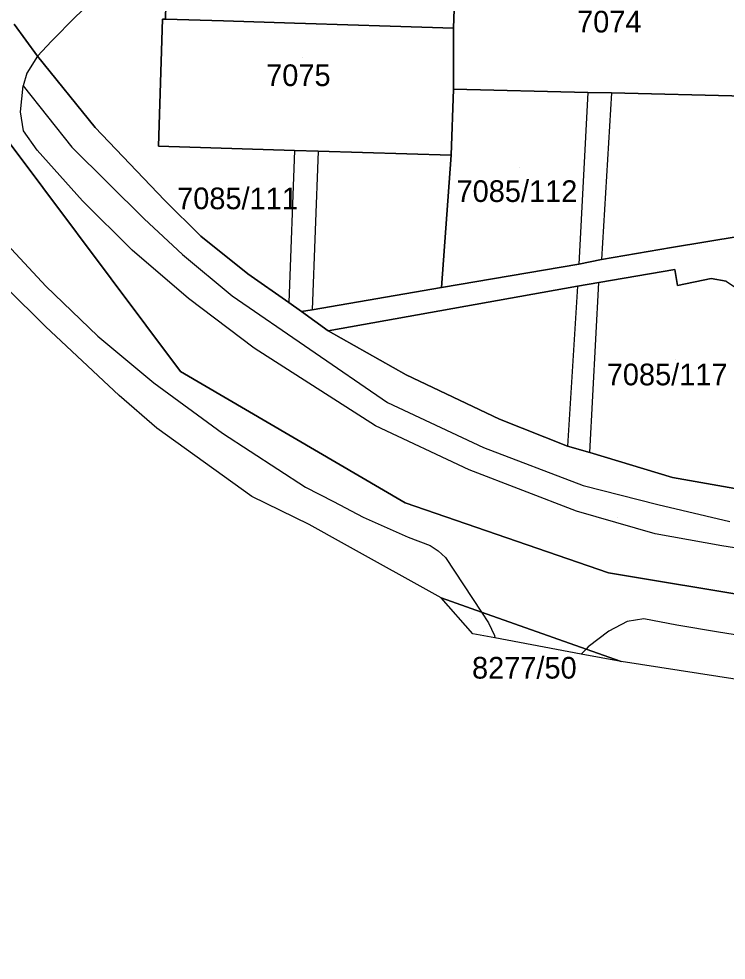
# Model space of a CAD drawing. Extents: x -266199 to -261993, y -1239047 to -1235108.
# Drawn here: x -263858.6 to -263793.2, y -1236874.8 to -1236787.9 of the extents above; entities that cross this region are included whole.
import ezdxf

# ---------------------------------------------------------------- set-up
doc = ezdxf.new("R2010")
doc.units = 0
for name, color, linetype in [('body_kn', 7, 'Continuous'), ('kladpar_druhypozemkov', 7, 'Continuous'), ('kladpar_hranice', 7, 'Continuous'), ('kladpar_parcelnecisla', 7, 'Continuous'), ('kladpar_plochy', 7, 'Continuous'), ('kladpar_sipky', 7, 'Continuous'), ('zappar_hrandruhpozemk', 7, 'Continuous'), ('zuob_linie', 7, 'Continuous'), ('zuob_plochy', 7, 'Continuous')]:
    doc.layers.add(name, color=color, linetype=linetype)

msp = doc.modelspace()

# ---------------------------------------------------------------- linework, layer by layer
at = {"layer": 'body_kn'}
for p, q in [((-263845.31, -1236787.91), (-263845.31, -1236787.91)), ((-263845.01, -1236787.92), (-263845.01, -1236787.92)), ((-263839.66, -1236788.08), (-263839.66, -1236788.08)), ((-263833.11, -1236788.28), (-263833.11, -1236788.28)), ((-263832.09, -1236788.32), (-263832.09, -1236788.32)), ((-263824.27, -1236788.56), (-263824.27, -1236788.56)), ((-263818.42, -1236788.74), (-263818.42, -1236788.74)), ((-263855.54, -1236789.94), (-263855.54, -1236789.94)), ((-263856.84, -1236791.34), (-263856.84, -1236791.34)), ((-263856.84, -1236791.34), (-263856.84, -1236791.34)), ((-263857.81, -1236792.91), (-263857.81, -1236792.91)), ((-263858.17, -1236794.08), (-263858.17, -1236794.08)), ((-263818.43, -1236794.38), (-263818.43, -1236794.38)), ((-263818.43, -1236794.38), (-263818.43, -1236794.38)), ((-263806.03, -1236794.67), (-263806.03, -1236794.67)), ((-263806.03, -1236794.67), (-263806.03, -1236794.67)), ((-263803.83, -1236794.72), (-263803.83, -1236794.72)), ((-263803.83, -1236794.72), (-263803.83, -1236794.72)), ((-263858.4, -1236796.46), (-263858.4, -1236796.46)), ((-263858.13, -1236798.23), (-263858.13, -1236798.23)), ((-263851.51, -1236797.91), (-263851.51, -1236797.91)), ((-263856.88, -1236800), (-263856.88, -1236800)), ((-263853.68, -1236799.72), (-263853.68, -1236799.72)), ((-263845.68, -1236799.65), (-263845.68, -1236799.65)), ((-263833.09, -1236800.04), (-263833.09, -1236800.04)), ((-263833.09, -1236800.04), (-263833.09, -1236800.04)), ((-263830.93, -1236800.11), (-263830.93, -1236800.11)), ((-263830.93, -1236800.11), (-263830.93, -1236800.11)), ((-263818.63, -1236800.48), (-263818.63, -1236800.48)), ((-263845.1, -1236804.61), (-263845.1, -1236804.61)), ((-263852.68, -1236804.68), (-263852.68, -1236804.68)), ((-263846.99, -1236806.36), (-263846.99, -1236806.36)), ((-263841.77, -1236807.94), (-263841.77, -1236807.94)), ((-263798.3, -1236809.01), (-263798.3, -1236809.01)), ((-263848.11, -1236809.25), (-263848.11, -1236809.25)), ((-263843.44, -1236809.64), (-263843.44, -1236809.64)), ((-263806.84, -1236810.54), (-263806.84, -1236810.54)), ((-263804.75, -1236810.1), (-263804.75, -1236810.1)), ((-263837.43, -1236811.44), (-263837.43, -1236811.44)), ((-263797.97, -1236811.03), (-263797.97, -1236811.03)), ((-263805, -1236812.24), (-263805, -1236812.24)), ((-263794.62, -1236811.86), (-263794.62, -1236811.86)), ((-263856.08, -1236812.58), (-263856.08, -1236812.58)), ((-263819.52, -1236812.7), (-263819.52, -1236812.7)), ((-263806.97, -1236812.58), (-263806.97, -1236812.58)), ((-263806.97, -1236812.58), (-263806.97, -1236812.58)), ((-263797.73, -1236812.51), (-263797.73, -1236812.51)), ((-263842.9, -1236813.7), (-263842.9, -1236813.7)), ((-263838.87, -1236813.47), (-263838.87, -1236813.47)), ((-263833.62, -1236814.06), (-263833.62, -1236814.06)), ((-263833.62, -1236814.06), (-263833.62, -1236814.06)), ((-263832.45, -1236814.91), (-263832.45, -1236814.91)), ((-263831.46, -1236814.74), (-263831.46, -1236814.74)), ((-263856.09, -1236816.3), (-263856.09, -1236816.3)), ((-263830.01, -1236816.68), (-263830.01, -1236816.68)), ((-263851.28, -1236817.18), (-263851.28, -1236817.18)), ((-263836.83, -1236818.29), (-263836.83, -1236818.29)), ((-263843.62, -1236820.44), (-263843.62, -1236820.44)), ((-263822.79, -1236820.75), (-263822.79, -1236820.75)), ((-263846.1, -1236821.49), (-263846.1, -1236821.49)), ((-263849.29, -1236822.67), (-263849.29, -1236822.67)), ((-263824.53, -1236823.31), (-263824.53, -1236823.31)), ((-263825.63, -1236825.45), (-263825.63, -1236825.45)), ((-263814.16, -1236824.84), (-263814.16, -1236824.84)), ((-263845.81, -1236825.69), (-263845.81, -1236825.69)), ((-263839.75, -1236826.15), (-263839.75, -1236826.15)), ((-263815.66, -1236827.45), (-263815.66, -1236827.45)), ((-263807.88, -1236827.35), (-263807.88, -1236827.35)), ((-263805.84, -1236827.92), (-263805.84, -1236827.92)), ((-263805.84, -1236827.92), (-263805.84, -1236827.92)), ((-263816.96, -1236829.51), (-263816.96, -1236829.51)), ((-263798.2, -1236830.24), (-263798.2, -1236830.24)), ((-263832.1, -1236831.11), (-263832.1, -1236831.11)), ((-263806.46, -1236830.98), (-263806.46, -1236830.98)), ((-263837.05, -1236831.98), (-263837.05, -1236831.98)), ((-263829.51, -1236832.44), (-263829.51, -1236832.44)), ((-263822.9, -1236832.57), (-263822.9, -1236832.57)), ((-263807.06, -1236833.33), (-263807.06, -1236833.33)), ((-263799.56, -1236832.73), (-263799.56, -1236832.73)), ((-263826.75, -1236833.88), (-263826.75, -1236833.88)), ((-263831.76, -1236834.58), (-263831.76, -1236834.58)), ((-263822.61, -1236835.73), (-263822.61, -1236835.73)), ((-263799.81, -1236835.43), (-263799.81, -1236835.43)), ((-263828.5, -1236836.39), (-263828.5, -1236836.39)), ((-263820.58, -1236836.51), (-263820.58, -1236836.51)), ((-263793.63, -1236836.55), (-263793.63, -1236836.55)), ((-263819.84, -1236837.01), (-263819.84, -1236837.01)), ((-263819.17, -1236837.61), (-263819.17, -1236837.61)), ((-263804.12, -1236839.05), (-263804.12, -1236839.05)), ((-263819.57, -1236841.35), (-263819.57, -1236841.35)), ((-263819.57, -1236841.35), (-263819.57, -1236841.35)), ((-263815.84, -1236842.66), (-263815.84, -1236842.66)), ((-263815.84, -1236842.66), (-263815.84, -1236842.66)), ((-263815.2, -1236843.64), (-263815.2, -1236843.64)), ((-263802.38, -1236843.52), (-263802.38, -1236843.52)), ((-263800.84, -1236843.28), (-263800.84, -1236843.28)), ((-263804.06, -1236844.42), (-263804.06, -1236844.42)), ((-263797.78, -1236843.88), (-263797.78, -1236843.88)), ((-263793.96, -1236844.51), (-263793.96, -1236844.51)), ((-263816.62, -1236844.67), (-263816.62, -1236844.67)), ((-263814.64, -1236844.83), (-263814.64, -1236844.83)), ((-263814.61, -1236845.04), (-263814.61, -1236845.04)), ((-263806.17, -1236846.07), (-263806.17, -1236846.07)), ((-263806.17, -1236846.07), (-263806.17, -1236846.07)), ((-263805.97, -1236845.87), (-263805.97, -1236845.87)), ((-263806.62, -1236846.53), (-263806.62, -1236846.53)), ((-263806.62, -1236846.53), (-263806.62, -1236846.53)), ((-263802.95, -1236847.21), (-263802.95, -1236847.21)), ((-263802.95, -1236847.21), (-263802.95, -1236847.21))]:
    msp.add_line(p, q, dxfattribs=at)
at = {"layer": 'kladpar_druhypozemkov'}
for p, q in [((-263832.33, -1236791.49), (-263832.33, -1236791.49)), ((-263812.3, -1236801.57), (-263812.3, -1236801.57)), ((-263839.19, -1236803.23), (-263839.19, -1236803.23)), ((-263797.92, -1236819.37), (-263797.92, -1236819.37)), ((-263819.45, -1236824.96), (-263819.45, -1236824.96)), ((-263803.24, -1236833.93), (-263803.24, -1236833.93)), ((-263816.75, -1236843.29), (-263816.75, -1236843.29))]:
    msp.add_line(p, q, dxfattribs=at)
at = {"layer": 'kladpar_hranice'}
msp.add_line((-263806.17, -1236846.07), (-263802.95, -1236847.21), dxfattribs=at)
for points in [[(-263885.56, -1236757.13), (-263885.06, -1236758.63), (-263884.31, -1236759.57), (-263883.19, -1236761.79), (-263882.75, -1236762.98), (-263881.19, -1236766.63), (-263876.49, -1236774.15), (-263874.06, -1236777.81), (-263869.37, -1236784.84), (-263868.51, -1236786.29), (-263862.79, -1236794.91), (-263843.62, -1236820.44), (-263822.9, -1236832.57), (-263804.12, -1236839.05), (-263748.03, -1236848.37), (-263745.45, -1236849.18), (-263737.14, -1236852.19), (-263733.47, -1236855.86), (-263713.69, -1236874.8)], [(-263713.69, -1236874.8), (-263733.47, -1236855.86), (-263737.14, -1236852.19), (-263745.45, -1236849.18), (-263748.03, -1236848.37), (-263804.12, -1236839.05), (-263822.9, -1236832.57), (-263843.62, -1236820.44), (-263862.79, -1236794.91), (-263868.51, -1236786.29), (-263869.37, -1236784.84), (-263874.06, -1236777.81), (-263876.49, -1236774.15), (-263881.19, -1236766.63), (-263882.75, -1236762.98), (-263883.19, -1236761.79), (-263884.31, -1236759.57), (-263885.06, -1236758.63)], [(-263818.19, -1236782.57), (-263818.42, -1236788.74), (-263824.27, -1236788.56), (-263832.09, -1236788.32), (-263833.11, -1236788.28), (-263839.66, -1236788.08), (-263845.01, -1236787.92), (-263845, -1236786.57)], [(-263818.19, -1236782.57), (-263812.37, -1236782.71), (-263805.98, -1236782.86), (-263804.93, -1236782.88), (-263797.06, -1236783.07), (-263791.21, -1236783.21), (-263791.29, -1236788.79), (-263791.48, -1236795.01), (-263803.83, -1236794.72), (-263806.03, -1236794.67), (-263818.43, -1236794.38), (-263818.42, -1236788.74), (-263818.19, -1236782.57)], [(-263845, -1236786.57), (-263845.01, -1236787.92), (-263845.31, -1236787.91), (-263845.68, -1236799.65), (-263833.09, -1236800.04), (-263830.93, -1236800.11), (-263818.63, -1236800.48), (-263819.52, -1236812.7), (-263831.46, -1236814.74), (-263832.45, -1236814.91), (-263833.62, -1236814.06)], [(-263853.29, -1236787.68), (-263855.54, -1236789.94), (-263856.84, -1236791.34), (-263858.99, -1236788.36)], [(-263833.62, -1236814.06), (-263837.43, -1236811.44), (-263841.77, -1236807.94), (-263845.1, -1236804.61), (-263851.51, -1236797.91), (-263856.84, -1236791.34), (-263855.54, -1236789.94), (-263853.29, -1236787.68)], [(-263818.43, -1236794.38), (-263818.63, -1236800.48), (-263830.93, -1236800.11), (-263833.09, -1236800.04), (-263845.68, -1236799.65), (-263845.31, -1236787.91), (-263845.01, -1236787.92), (-263839.66, -1236788.08), (-263833.11, -1236788.28), (-263832.09, -1236788.32), (-263824.27, -1236788.56), (-263818.42, -1236788.74), (-263818.43, -1236794.38)], [(-263858.99, -1236788.36), (-263856.84, -1236791.34), (-263851.51, -1236797.91), (-263845.1, -1236804.61), (-263841.77, -1236807.94), (-263837.43, -1236811.44), (-263833.62, -1236814.06), (-263832.45, -1236814.91), (-263830.01, -1236816.68), (-263822.79, -1236820.75), (-263814.16, -1236824.84), (-263807.88, -1236827.35), (-263805.84, -1236827.92), (-263798.2, -1236830.24), (-263792.43, -1236831.24)], [(-263819.57, -1236841.35), (-263828.5, -1236836.39), (-263831.76, -1236834.58), (-263837.05, -1236831.98), (-263845.81, -1236825.69), (-263849.29, -1236822.67), (-263856.09, -1236816.3), (-263863.4, -1236809.08), (-263872.33, -1236797.86), (-263876.36, -1236792.79)], [(-263791.48, -1236795.01), (-263791.95, -1236807.94), (-263798.3, -1236809.01), (-263804.75, -1236810.1), (-263806.84, -1236810.54), (-263819.52, -1236812.7), (-263818.63, -1236800.48), (-263818.43, -1236794.38), (-263806.03, -1236794.67), (-263803.83, -1236794.72), (-263791.48, -1236795.01)], [(-263793.23, -1236812.11), (-263794.62, -1236811.86), (-263797.73, -1236812.51), (-263797.97, -1236811.03), (-263805, -1236812.24), (-263806.97, -1236812.58), (-263830.01, -1236816.68), (-263832.45, -1236814.91), (-263831.46, -1236814.74), (-263819.52, -1236812.7), (-263806.84, -1236810.54), (-263804.75, -1236810.1), (-263798.3, -1236809.01), (-263791.95, -1236807.94)], [(-263791.97, -1236831.32), (-263792.43, -1236831.24), (-263798.2, -1236830.24), (-263805.84, -1236827.92), (-263807.88, -1236827.35), (-263814.16, -1236824.84), (-263822.79, -1236820.75), (-263830.01, -1236816.68), (-263806.97, -1236812.58), (-263805, -1236812.24), (-263797.97, -1236811.03), (-263797.73, -1236812.51), (-263794.62, -1236811.86), (-263793.23, -1236812.11), (-263792.48, -1236812.64), (-263791.74, -1236813.43), (-263791.4, -1236814.41), (-263791.39, -1236816.72), (-263791.83, -1236816.71), (-263791.98, -1236828.59), (-263791.97, -1236831.32)], [(-263802.95, -1236847.21), (-263806.17, -1236846.07), (-263815.84, -1236842.66), (-263819.57, -1236841.35)], [(-263802.95, -1236847.21), (-263806.62, -1236846.53), (-263814.61, -1236845.04), (-263816.62, -1236844.67), (-263819.57, -1236841.35)], [(-263819.57, -1236841.35), (-263815.84, -1236842.66), (-263806.17, -1236846.07)], [(-263775.1, -1236851.48), (-263781.92, -1236850.49), (-263802.95, -1236847.21)]]:
    msp.add_lwpolyline(points, dxfattribs=at)
at = {"layer": 'kladpar_plochy'}
for points in [[(-263818.19, -1236782.57), (-263818.42, -1236788.74), (-263824.27, -1236788.56), (-263832.09, -1236788.32), (-263833.11, -1236788.28), (-263839.66, -1236788.08), (-263845.01, -1236787.92), (-263845, -1236786.57)], [(-263853.29, -1236787.68), (-263855.54, -1236789.94), (-263856.84, -1236791.34), (-263858.99, -1236788.36)], [(-263858.99, -1236788.36), (-263856.84, -1236791.34), (-263851.51, -1236797.91), (-263845.1, -1236804.61), (-263841.77, -1236807.94), (-263837.43, -1236811.44), (-263833.62, -1236814.06), (-263832.45, -1236814.91), (-263830.01, -1236816.68), (-263822.79, -1236820.75), (-263814.16, -1236824.84), (-263807.88, -1236827.35), (-263805.84, -1236827.92), (-263798.2, -1236830.24), (-263792.43, -1236831.24)], [(-263862.79, -1236794.91), (-263843.62, -1236820.44), (-263822.9, -1236832.57), (-263804.12, -1236839.05), (-263748.03, -1236848.37), (-263745.45, -1236849.18), (-263737.14, -1236852.19), (-263733.47, -1236855.86), (-263713.69, -1236874.8)], [(-263713.69, -1236874.8), (-263733.47, -1236855.86), (-263737.14, -1236852.19), (-263745.45, -1236849.18), (-263748.03, -1236848.37), (-263804.12, -1236839.05), (-263822.9, -1236832.57), (-263843.62, -1236820.44), (-263862.79, -1236794.91)], [(-263793.23, -1236812.11), (-263794.62, -1236811.86), (-263797.73, -1236812.51), (-263797.97, -1236811.03), (-263805, -1236812.24), (-263806.97, -1236812.58), (-263830.01, -1236816.68), (-263832.45, -1236814.91), (-263831.46, -1236814.74), (-263819.52, -1236812.7), (-263806.84, -1236810.54), (-263804.75, -1236810.1), (-263798.3, -1236809.01), (-263791.95, -1236807.94)], [(-263728.97, -1236869.65), (-263737.56, -1236862.77), (-263739.57, -1236861.16), (-263741.53, -1236860.42), (-263756.43, -1236854.8), (-263769.54, -1236852.39), (-263775.1, -1236851.48), (-263781.92, -1236850.49), (-263802.95, -1236847.21), (-263806.17, -1236846.07), (-263815.84, -1236842.66), (-263819.57, -1236841.35), (-263828.5, -1236836.39), (-263831.76, -1236834.58), (-263837.05, -1236831.98), (-263845.81, -1236825.69), (-263849.29, -1236822.67), (-263856.09, -1236816.3), (-263863.4, -1236809.08)]]:
    msp.add_lwpolyline(points, dxfattribs=at)
for points in [[(-263818.19, -1236782.57), (-263812.37, -1236782.71), (-263805.98, -1236782.86), (-263804.93, -1236782.88), (-263797.06, -1236783.07), (-263791.21, -1236783.21), (-263791.29, -1236788.79), (-263791.48, -1236795.01), (-263803.83, -1236794.72), (-263806.03, -1236794.67), (-263818.43, -1236794.38), (-263818.42, -1236788.74)], [(-263833.62, -1236814.06), (-263837.43, -1236811.44), (-263841.77, -1236807.94), (-263845.1, -1236804.61), (-263851.51, -1236797.91), (-263856.84, -1236791.34), (-263855.54, -1236789.94), (-263853.29, -1236787.68), (-263851.99, -1236786.42), (-263850.52, -1236785.37), (-263848.53, -1236784.42), (-263847.69, -1236784.27), (-263846.53, -1236784.6), (-263845.53, -1236785.47), (-263845, -1236786.57), (-263845.01, -1236787.92), (-263845.31, -1236787.91), (-263845.68, -1236799.65), (-263833.09, -1236800.04), (-263830.93, -1236800.11), (-263818.63, -1236800.48), (-263819.52, -1236812.7), (-263831.46, -1236814.74), (-263832.45, -1236814.91)], [(-263818.43, -1236794.38), (-263818.63, -1236800.48), (-263830.93, -1236800.11), (-263833.09, -1236800.04), (-263845.68, -1236799.65), (-263845.31, -1236787.91), (-263845.01, -1236787.92), (-263839.66, -1236788.08), (-263833.11, -1236788.28), (-263832.09, -1236788.32), (-263824.27, -1236788.56), (-263818.42, -1236788.74)], [(-263791.48, -1236795.01), (-263791.95, -1236807.94), (-263798.3, -1236809.01), (-263804.75, -1236810.1), (-263806.84, -1236810.54), (-263819.52, -1236812.7), (-263818.63, -1236800.48), (-263818.43, -1236794.38), (-263806.03, -1236794.67), (-263803.83, -1236794.72)], [(-263791.97, -1236831.32), (-263792.43, -1236831.24), (-263798.2, -1236830.24), (-263805.84, -1236827.92), (-263807.88, -1236827.35), (-263814.16, -1236824.84), (-263822.79, -1236820.75), (-263830.01, -1236816.68), (-263806.97, -1236812.58), (-263805, -1236812.24), (-263797.97, -1236811.03), (-263797.73, -1236812.51), (-263794.62, -1236811.86), (-263793.23, -1236812.11), (-263792.48, -1236812.64), (-263791.74, -1236813.43), (-263791.4, -1236814.41), (-263791.39, -1236816.72), (-263791.83, -1236816.71), (-263791.98, -1236828.59)], [(-263806.17, -1236846.07), (-263802.95, -1236847.21), (-263806.62, -1236846.53), (-263814.61, -1236845.04), (-263816.62, -1236844.67), (-263819.57, -1236841.35), (-263815.84, -1236842.66)]]:
    msp.add_lwpolyline(points, close=True, dxfattribs=at)
at = {"layer": 'kladpar_sipky'}
msp.add_line((-263815.68, -1236844.43), (-263815.68, -1236844.43), dxfattribs=at)
at = {"layer": 'zappar_hrandruhpozemk'}
for p, q in [((-263806.03, -1236794.67), (-263806.84, -1236810.54)), ((-263803.83, -1236794.72), (-263804.75, -1236810.1)), ((-263853.68, -1236799.72), (-263846.99, -1236806.36)), ((-263833.09, -1236800.04), (-263833.62, -1236814.06)), ((-263830.93, -1236800.11), (-263831.46, -1236814.74)), ((-263842.9, -1236813.7), (-263848.11, -1236809.25)), ((-263805.84, -1236827.92), (-263805, -1236812.24)), ((-263806.97, -1236812.58), (-263807.88, -1236827.35)), ((-263838.87, -1236813.47), (-263824.53, -1236823.31)), ((-263839.75, -1236826.15), (-263832.1, -1236831.11)), ((-263799.56, -1236832.73), (-263792.91, -1236834.31)), ((-263793.63, -1236836.55), (-263799.81, -1236835.43)), ((-263781.05, -1236846.57), (-263793.96, -1236844.51)), ((-263806.62, -1236846.53), (-263806.17, -1236846.07)), ((-263805.97, -1236845.87), (-263806.17, -1236846.07))]:
    msp.add_line(p, q, dxfattribs=at)
for points in [[(-263856.84, -1236791.34), (-263857.81, -1236792.91), (-263858.17, -1236794.08)], [(-263848.11, -1236809.25), (-263852.68, -1236804.68), (-263856.88, -1236800), (-263858.13, -1236798.23), (-263858.4, -1236796.46), (-263858.17, -1236794.08), (-263853.68, -1236799.72)], [(-263869.49, -1236796.73), (-263865.16, -1236802.33), (-263860.88, -1236807.41), (-263856.08, -1236812.58), (-263851.28, -1236817.18), (-263846.1, -1236821.49), (-263839.75, -1236826.15)], [(-263846.99, -1236806.36), (-263843.44, -1236809.64), (-263838.87, -1236813.47)], [(-263799.81, -1236835.43), (-263807.06, -1236833.33), (-263816.96, -1236829.51), (-263825.63, -1236825.45), (-263836.83, -1236818.29), (-263842.9, -1236813.7)], [(-263824.53, -1236823.31), (-263815.66, -1236827.45), (-263806.46, -1236830.98), (-263799.56, -1236832.73)], [(-263832.1, -1236831.11), (-263829.51, -1236832.44), (-263826.75, -1236833.88), (-263822.61, -1236835.73), (-263820.58, -1236836.51), (-263819.84, -1236837.01), (-263819.17, -1236837.61), (-263815.84, -1236842.66)], [(-263772.29, -1236840.01), (-263778.81, -1236838.79), (-263786.98, -1236837.59), (-263793.63, -1236836.55)], [(-263815.84, -1236842.66), (-263815.2, -1236843.64), (-263814.64, -1236844.83), (-263814.61, -1236845.04)], [(-263793.96, -1236844.51), (-263797.78, -1236843.88), (-263800.84, -1236843.28), (-263802.38, -1236843.52), (-263804.06, -1236844.42), (-263805.97, -1236845.87)]]:
    msp.add_lwpolyline(points, dxfattribs=at)
at = {"layer": 'zuob_linie'}
msp.add_lwpolyline([(-263730.31, -1236871.57), (-263733.77, -1236869.03), (-263736.73, -1236866.59), (-263739.58, -1236864.77), (-263740.93, -1236863.91), (-263744.37, -1236861.76), (-263747.4, -1236860.08), (-263755.9, -1236857.2), (-263775.1, -1236851.48), (-263781.92, -1236850.49), (-263802.95, -1236847.21), (-263806.62, -1236846.53), (-263814.61, -1236845.04), (-263816.62, -1236844.67), (-263819.57, -1236841.35), (-263828.5, -1236836.39), (-263831.76, -1236834.58), (-263837.05, -1236831.98), (-263845.81, -1236825.69), (-263849.29, -1236822.67), (-263856.09, -1236816.3), (-263863.4, -1236809.08)], dxfattribs=at)
at = {"layer": 'zuob_plochy'}
msp.add_lwpolyline([(-263730.31, -1236871.57), (-263733.77, -1236869.03), (-263736.73, -1236866.59), (-263739.58, -1236864.77), (-263740.93, -1236863.91), (-263744.37, -1236861.76), (-263747.4, -1236860.08), (-263755.9, -1236857.2), (-263775.1, -1236851.48), (-263781.92, -1236850.49), (-263802.95, -1236847.21), (-263806.62, -1236846.53), (-263814.61, -1236845.04), (-263816.62, -1236844.67), (-263819.57, -1236841.35), (-263828.5, -1236836.39), (-263831.76, -1236834.58), (-263837.05, -1236831.98), (-263845.81, -1236825.69), (-263849.29, -1236822.67), (-263856.09, -1236816.3), (-263863.4, -1236809.08)], dxfattribs=at)

# ---------------------------------------------------------------- texts
at = {"layer": 'kladpar_parcelnecisla'}
for s, p in [('7074', (-263807.007, -1236789.14)), ('7075', (-263835.722, -1236794.09)), ('7085/112', (-263818.14, -1236804.79)), ('7085/111', (-263843.944, -1236805.46)), ('7085/117', (-263804.267, -1236821.72)), ('8277/50', (-263816.711, -1236848.8))]:
    msp.add_text(s, height=2, dxfattribs=at).set_placement(p)

doc.saveas('drawing.dxf')
